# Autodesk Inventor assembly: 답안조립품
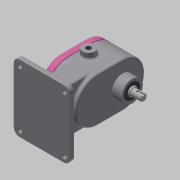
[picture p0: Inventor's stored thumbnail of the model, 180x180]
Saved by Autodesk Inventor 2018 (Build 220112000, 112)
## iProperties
Created: 2020-09
Part Number: 답안조립품
Material: 일반
Document SubType Name: Assembly
Designer: home
Author: home
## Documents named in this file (11)
- C:\Users\home\Desktop\700906V1031\답안조립품.iam
- C:\Users\home\Desktop\700906V1031\본체.ipt
- C:\Users\home\Desktop\700906V1031\베어링부시.ipt
- C:\Users\home\Desktop\700906V1031\스퍼기어.ipt
- C:\Users\home\Desktop\700906V1031\서브축.ipt
- C:\Users\home\Desktop\700906V1031\메인축.ipt
- C:\Users\home\Desktop\700906V1031\키 6 x 6 x 18.ipt
- C:\Users\home\Desktop\700906V1031\커버.ipt
- C:\Users\home\Desktop\700906V1031\볼트 M5.ipt
- C:\Users\home\Desktop\700906V1031\오일 실 16 28 7.ipt
- C:\Users\home\Desktop\700906V1031\개스킷.ipt
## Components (1 placed, 1 different names)
1. 개스킷:1
